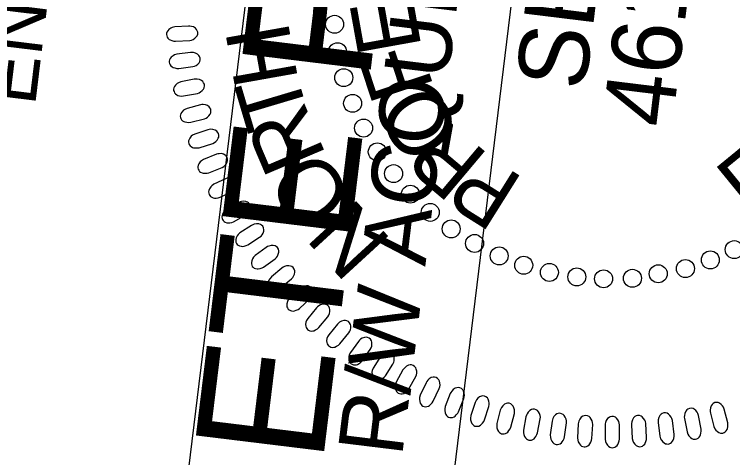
# Model space of a CAD drawing. Extents: x 480344 to 482186, y 488805 to 491553.
# Drawn here: x 480882.7 to 480946.7, y 490486.4 to 490525.8 of the extents above; entities that cross this region are included whole.
import ezdxf

# ---------------------------------------------------------------- set-up
doc = ezdxf.new("R2010")
doc.units = 0
for name, color, linetype in [('Sheet PE Seal Cell', 7, 'Continuous'), ('Sheet Plan CELL', 7, 'Continuous'), ('Sheet Sticker Incomplete CELL', 7, 'Continuous')]:
    doc.layers.add(name, color=color, linetype=linetype)

msp = doc.modelspace()

# ---------------------------------------------------------------- linework, layer by layer
at = {"layer": 'Sheet PE Seal Cell'}
for points in [[(480898.231, 490524.802), (480897.008, 490524.72), (480896.791, 490524.668), (480896.655, 490524.607), (480896.494, 490524.483), (480896.391, 490524.38), (480896.318, 490524.262), (480896.286, 490524.155), (480896.273, 490524.042), (480896.3, 490523.931), (480896.339, 490523.814), (480896.405, 490523.714), (480896.512, 490523.615), (480896.595, 490523.561), (480896.749, 490523.504), (480896.932, 490523.457), (480897.093, 490523.445), (480898.347, 490523.521), (480898.515, 490523.555), (480898.651, 490523.608), (480898.804, 490523.709), (480898.936, 490523.83), (480899.009, 490523.932), (480899.058, 490524.093), (480899.068, 490524.243), (480899.018, 490524.39), (480898.962, 490524.491), (480898.854, 490524.611), (480898.677, 490524.719), (480898.493, 490524.774), (480898.362, 490524.795)], [(480898.421, 490522.456), (480897.204, 490522.298), (480896.992, 490522.233), (480896.859, 490522.163), (480896.706, 490522.029), (480896.61, 490521.919), (480896.545, 490521.798), (480896.519, 490521.688), (480896.514, 490521.575), (480896.548, 490521.466), (480896.593, 490521.351), (480896.666, 490521.255), (480896.779, 490521.164), (480896.865, 490521.115), (480897.023, 490521.068), (480897.208, 490521.032), (480897.369, 490521.03), (480898.616, 490521.185), (480898.781, 490521.229), (480898.914, 490521.292), (480899.061, 490521.401), (480899.185, 490521.531), (480899.251, 490521.637), (480899.291, 490521.801), (480899.291, 490521.951), (480899.232, 490522.095), (480899.169, 490522.192), (480899.054, 490522.305), (480898.87, 490522.401), (480898.683, 490522.445), (480898.552, 490522.458)], [(480898.754, 490520.065), (480897.55, 490519.83), (480897.342, 490519.752), (480897.215, 490519.674), (480897.069, 490519.531), (480896.98, 490519.415), (480896.923, 490519.29), (480896.904, 490519.179), (480896.906, 490519.065), (480896.947, 490518.959), (480896.999, 490518.848), (480897.078, 490518.756), (480897.196, 490518.672), (480897.286, 490518.629), (480897.445, 490518.591), (480897.633, 490518.567), (480897.794, 490518.575), (480899.029, 490518.808), (480899.191, 490518.863), (480899.319, 490518.934), (480899.459, 490519.052), (480899.574, 490519.189), (480899.634, 490519.299), (480899.663, 490519.465), (480899.654, 490519.615), (480899.586, 490519.755), (480899.517, 490519.848), (480899.395, 490519.953), (480899.206, 490520.038), (480899.017, 490520.07), (480898.884, 490520.075)], [(480899.297, 490517.781), (480898.11, 490517.471), (480897.907, 490517.38), (480897.785, 490517.294), (480897.65, 490517.143), (480897.568, 490517.021), (480897.519, 490516.893), (480897.507, 490516.781), (480897.517, 490516.668), (480897.564, 490516.564), (480897.623, 490516.456), (480897.707, 490516.37), (480897.83, 490516.293), (480897.922, 490516.256), (480898.084, 490516.228), (480898.273, 490516.216), (480898.433, 490516.234), (480899.651, 490516.545), (480899.809, 490516.609), (480899.933, 490516.688), (480900.065, 490516.815), (480900.171, 490516.958), (480900.224, 490517.072), (480900.243, 490517.24), (480900.224, 490517.389), (480900.147, 490517.524), (480900.073, 490517.612), (480899.944, 490517.71), (480899.75, 490517.784), (480899.559, 490517.803), (480899.426, 490517.799)], [(480899.967, 490515.566), (480898.801, 490515.183), (480898.605, 490515.079), (480898.488, 490514.985), (480898.362, 490514.826), (480898.289, 490514.699), (480898.248, 490514.568), (480898.243, 490514.456), (480898.259, 490514.343), (480898.313, 490514.243), (480898.378, 490514.139), (480898.468, 490514.058), (480898.595, 490513.989), (480898.69, 490513.958), (480898.853, 490513.94), (480899.043, 490513.94), (480899.201, 490513.968), (480900.396, 490514.354), (480900.551, 490514.428), (480900.67, 490514.515), (480900.793, 490514.65), (480900.891, 490514.8), (480900.936, 490514.917), (480900.943, 490515.085), (480900.916, 490515.234), (480900.831, 490515.363), (480900.751, 490515.447), (480900.617, 490515.536), (480900.419, 490515.597), (480900.227, 490515.605), (480900.094, 490515.593)], [(480900.721, 490513.376), (480899.582, 490512.919), (480899.391, 490512.803), (480899.282, 490512.703), (480899.166, 490512.536), (480899.1, 490512.405), (480899.067, 490512.271), (480899.07, 490512.159), (480899.093, 490512.048), (480899.153, 490511.951), (480899.225, 490511.851), (480899.319, 490511.776), (480899.451, 490511.716), (480899.547, 490511.69), (480899.711, 490511.683), (480899.9, 490511.694), (480900.057, 490511.733), (480901.226, 490512.193), (480901.375, 490512.277), (480901.488, 490512.371), (480901.602, 490512.513), (480901.691, 490512.669), (480901.729, 490512.789), (480901.726, 490512.957), (480901.689, 490513.103), (480901.596, 490513.227), (480901.511, 490513.306), (480901.371, 490513.387), (480901.169, 490513.434), (480900.978, 490513.43), (480900.846, 490513.41)], [(480901.61, 490511.235), (480900.502, 490510.708), (480900.319, 490510.58), (480900.216, 490510.473), (480900.11, 490510.299), (480900.053, 490510.164), (480900.029, 490510.029), (480900.038, 490509.917), (480900.069, 490509.807), (480900.134, 490509.714), (480900.213, 490509.619), (480900.312, 490509.55), (480900.447, 490509.499), (480900.544, 490509.479), (480900.709, 490509.482), (480900.896, 490509.506), (480901.05, 490509.553), (480902.189, 490510.086), (480902.332, 490510.179), (480902.439, 490510.28), (480902.544, 490510.429), (480902.622, 490510.59), (480902.653, 490510.712), (480902.639, 490510.88), (480902.593, 490511.023), (480902.493, 490511.141), (480902.403, 490511.215), (480902.259, 490511.287), (480902.054, 490511.322), (480901.862, 490511.305), (480901.733, 490511.277)], [(480902.712, 490509.085), (480901.639, 490508.489), (480901.465, 490508.35), (480901.368, 490508.237), (480901.274, 490508.056), (480901.226, 490507.918), (480901.21, 490507.782), (480901.226, 490507.67), (480901.263, 490507.563), (480901.335, 490507.475), (480901.419, 490507.385), (480901.522, 490507.322), (480901.66, 490507.279), (480901.759, 490507.265), (480901.923, 490507.279), (480902.108, 490507.314), (480902.259, 490507.372), (480903.361, 490507.974), (480903.499, 490508.077), (480903.599, 490508.183), (480903.695, 490508.339), (480903.763, 490508.505), (480903.786, 490508.629), (480903.762, 490508.795), (480903.706, 490508.935), (480903.599, 490509.047), (480903.505, 490509.114), (480903.356, 490509.177), (480903.15, 490509.199), (480902.96, 490509.171), (480902.832, 490509.134)], [(480903.862, 490507.049), (480902.829, 490506.388), (480902.665, 490506.238), (480902.575, 490506.119), (480902.493, 490505.933), (480902.452, 490505.793), (480902.446, 490505.655), (480902.469, 490505.545), (480902.513, 490505.44), (480902.59, 490505.356), (480902.68, 490505.272), (480902.786, 490505.215), (480902.927, 490505.181), (480903.026, 490505.174), (480903.189, 490505.198), (480903.372, 490505.244), (480903.519, 490505.312), (480904.581, 490505.982), (480904.712, 490506.093), (480904.805, 490506.206), (480904.891, 490506.367), (480904.948, 490506.537), (480904.963, 490506.662), (480904.929, 490506.827), (480904.865, 490506.963), (480904.75, 490507.067), (480904.652, 490507.129), (480904.5, 490507.182), (480904.293, 490507.191), (480904.105, 490507.151), (480903.98, 490507.106)], [(480905.173, 490505.088), (480904.184, 490504.364), (480904.028, 490504.204), (480903.946, 490504.079), (480903.876, 490503.888), (480903.845, 490503.746), (480903.847, 490503.608), (480903.877, 490503.5), (480903.927, 490503.397), (480904.009, 490503.319), (480904.104, 490503.24), (480904.214, 490503.191), (480904.357, 490503.165), (480904.456, 490503.164), (480904.617, 490503.198), (480904.797, 490503.256), (480904.938, 490503.332), (480905.957, 490504.069), (480906.081, 490504.187), (480906.166, 490504.305), (480906.242, 490504.472), (480906.289, 490504.646), (480906.296, 490504.771), (480906.251, 490504.933), (480906.179, 490505.065), (480906.058, 490505.162), (480905.956, 490505.217), (480905.801, 490505.261), (480905.594, 490505.258), (480905.409, 490505.205), (480905.287, 490505.153)], [(480906.569, 490503.243), (480905.627, 490502.458), (480905.482, 490502.288), (480905.409, 490502.159), (480905.35, 490501.964), (480905.328, 490501.819), (480905.339, 490501.682), (480905.375, 490501.576), (480905.432, 490501.477), (480905.518, 490501.404), (480905.618, 490501.331), (480905.731, 490501.289), (480905.875, 490501.272), (480905.974, 490501.278), (480906.133, 490501.321), (480906.308, 490501.391), (480906.446, 490501.475), (480907.416, 490502.275), (480907.531, 490502.4), (480907.61, 490502.524), (480907.675, 490502.696), (480907.71, 490502.871), (480907.71, 490502.997), (480907.655, 490503.156), (480907.574, 490503.283), (480907.448, 490503.372), (480907.343, 490503.421), (480907.185, 490503.455), (480906.978, 490503.438), (480906.797, 490503.375), (480906.679, 490503.315)], [(480908.147, 490501.425), (480907.256, 490500.582), (480907.123, 490500.404), (480907.057, 490500.27), (480907.011, 490500.072), (480906.998, 490499.926), (480907.017, 490499.79), (480907.06, 490499.687), (480907.123, 490499.591), (480907.214, 490499.523), (480907.319, 490499.458), (480907.433, 490499.422), (480907.578, 490499.415), (480907.677, 490499.426), (480907.832, 490499.48), (480908.004, 490499.56), (480908.135, 490499.653), (480909.053, 490500.512), (480909.161, 490500.645), (480909.231, 490500.773), (480909.285, 490500.948), (480909.309, 490501.125), (480909.3, 490501.251), (480909.236, 490501.406), (480909.148, 490501.528), (480909.016, 490501.609), (480908.908, 490501.651), (480908.748, 490501.675), (480908.543, 490501.645), (480908.366, 490501.571), (480908.252, 490501.503)], [(480909.652, 490499.705), (480908.866, 490498.764), (480908.755, 490498.571), (480908.705, 490498.43), (480908.683, 490498.228), (480908.687, 490498.082), (480908.722, 490497.949), (480908.777, 490497.852), (480908.85, 490497.764), (480908.949, 490497.707), (480909.06, 490497.654), (480909.179, 490497.632), (480909.323, 490497.642), (480909.42, 490497.665), (480909.567, 490497.737), (480909.729, 490497.837), (480909.848, 490497.945), (480910.659, 490498.905), (480910.75, 490499.049), (480910.805, 490499.185), (480910.838, 490499.366), (480910.842, 490499.544), (480910.817, 490499.668), (480910.736, 490499.814), (480910.634, 490499.925), (480910.493, 490499.991), (480910.381, 490500.019), (480910.22, 490500.024), (480910.02, 490499.971), (480909.853, 490499.876), (480909.747, 490499.795)], [(480911.513, 490498.255), (480910.735, 490497.307), (480910.624, 490497.114), (480910.576, 490496.973), (480910.554, 490496.77), (480910.56, 490496.623), (480910.596, 490496.491), (480910.652, 490496.394), (480910.726, 490496.307), (480910.826, 490496.251), (480910.937, 490496.199), (480911.056, 490496.178), (480911.2, 490496.189), (480911.297, 490496.212), (480911.444, 490496.286), (480911.604, 490496.386), (480911.722, 490496.496), (480912.525, 490497.462), (480912.616, 490497.608), (480912.67, 490497.744), (480912.701, 490497.924), (480912.703, 490498.103), (480912.679, 490498.226), (480912.595, 490498.372), (480912.492, 490498.482), (480912.352, 490498.546), (480912.239, 490498.574), (480912.077, 490498.578), (480911.878, 490498.523), (480911.712, 490498.427), (480911.606, 490498.346)], [(480913.389, 490496.712), (480912.671, 490495.717), (480912.574, 490495.518), (480912.534, 490495.373), (480912.526, 490495.17), (480912.541, 490495.024), (480912.585, 490494.894), (480912.647, 490494.801), (480912.726, 490494.719), (480912.829, 490494.67), (480912.943, 490494.624), (480913.063, 490494.611), (480913.206, 490494.631), (480913.301, 490494.661), (480913.443, 490494.743), (480913.597, 490494.853), (480913.709, 490494.97), (480914.449, 490495.985), (480914.53, 490496.135), (480914.575, 490496.275), (480914.596, 490496.457), (480914.587, 490496.636), (480914.554, 490496.757), (480914.462, 490496.898), (480914.352, 490497.001), (480914.208, 490497.056), (480914.094, 490497.077), (480913.932, 490497.071), (480913.736, 490497.003), (480913.577, 490496.897), (480913.477, 490496.809)], [(480915.363, 490495.354), (480914.709, 490494.316), (480914.624, 490494.111), (480914.593, 490493.964), (480914.598, 490493.761), (480914.622, 490493.616), (480914.675, 490493.489), (480914.742, 490493.4), (480914.826, 490493.323), (480914.932, 490493.28), (480915.049, 490493.242), (480915.169, 490493.237), (480915.311, 490493.266), (480915.404, 490493.301), (480915.541, 490493.392), (480915.687, 490493.512), (480915.791, 490493.635), (480916.467, 490494.695), (480916.538, 490494.85), (480916.574, 490494.992), (480916.583, 490495.175), (480916.562, 490495.353), (480916.523, 490495.472), (480916.422, 490495.607), (480916.306, 490495.703), (480916.158, 490495.749), (480916.043, 490495.762), (480915.883, 490495.746), (480915.691, 490495.666), (480915.539, 490495.55), (480915.444, 490495.456)], [(480917.352, 490494.165), (480916.765, 490493.088), (480916.693, 490492.877), (480916.672, 490492.73), (480916.689, 490492.527), (480916.722, 490492.384), (480916.783, 490492.261), (480916.856, 490492.176), (480916.945, 490492.104), (480917.052, 490492.069), (480917.172, 490492.038), (480917.292, 490492.039), (480917.431, 490492.077), (480917.523, 490492.119), (480917.653, 490492.218), (480917.791, 490492.347), (480917.887, 490492.476), (480918.495, 490493.576), (480918.556, 490493.736), (480918.584, 490493.88), (480918.582, 490494.063), (480918.55, 490494.239), (480918.503, 490494.356), (480918.394, 490494.484), (480918.272, 490494.572), (480918.122, 490494.609), (480918.005, 490494.615), (480917.846, 490494.589), (480917.661, 490494.497), (480917.515, 490494.371), (480917.427, 490494.271)], [(480919.419, 490493.03), (480918.901, 490491.918), (480918.842, 490491.704), (480918.83, 490491.555), (480918.86, 490491.354), (480918.902, 490491.213), (480918.97, 490491.094), (480919.048, 490491.014), (480919.141, 490490.948), (480919.251, 490490.919), (480919.372, 490490.895), (480919.492, 490490.905), (480919.629, 490490.951), (480919.717, 490490.999), (480919.842, 490491.106), (480919.971, 490491.243), (480920.059, 490491.378), (480920.597, 490492.514), (480920.648, 490492.678), (480920.666, 490492.823), (480920.652, 490493.006), (480920.609, 490493.179), (480920.556, 490493.293), (480920.439, 490493.414), (480920.311, 490493.495), (480920.159, 490493.521), (480920.043, 490493.52), (480919.886, 490493.484), (480919.706, 490493.381), (480919.569, 490493.246), (480919.487, 490493.141)], [(480921.572, 490492.058), (480921.125, 490490.915), (480921.08, 490490.698), (480921.077, 490490.548), (480921.12, 490490.349), (480921.171, 490490.212), (480921.246, 490490.096), (480921.329, 490490.021), (480921.426, 490489.962), (480921.537, 490489.939), (480921.66, 490489.924), (480921.78, 490489.941), (480921.913, 490489.996), (480921.998, 490490.048), (480922.115, 490490.164), (480922.236, 490490.309), (480922.315, 490490.449), (480922.781, 490491.617), (480922.821, 490491.783), (480922.83, 490491.929), (480922.805, 490492.11), (480922.752, 490492.281), (480922.69, 490492.391), (480922.566, 490492.504), (480922.434, 490492.577), (480922.28, 490492.594), (480922.164, 490492.586), (480922.01, 490492.539), (480921.837, 490492.425), (480921.708, 490492.283), (480921.634, 490492.172)], [(480923.789, 490491.272), (480923.415, 490490.104), (480923.383, 490489.884), (480923.389, 490489.734), (480923.445, 490489.538), (480923.504, 490489.404), (480923.587, 490489.294), (480923.674, 490489.225), (480923.774, 490489.171), (480923.887, 490489.156), (480924.01, 490489.148), (480924.128, 490489.173), (480924.258, 490489.236), (480924.34, 490489.294), (480924.45, 490489.415), (480924.562, 490489.568), (480924.631, 490489.713), (480925.023, 490490.908), (480925.053, 490491.076), (480925.052, 490491.223), (480925.016, 490491.402), (480924.952, 490491.569), (480924.884, 490491.675), (480924.753, 490491.78), (480924.616, 490491.845), (480924.461, 490491.852), (480924.347, 490491.836), (480924.195, 490491.78), (480924.029, 490491.656), (480923.91, 490491.505), (480923.842, 490491.39)], [(480926.035, 490490.574), (480925.735, 490489.385), (480925.717, 490489.163), (480925.733, 490489.014), (480925.801, 490488.823), (480925.868, 490488.692), (480925.957, 490488.588), (480926.049, 490488.523), (480926.153, 490488.476), (480926.266, 490488.469), (480926.39, 490488.468), (480926.506, 490488.5), (480926.632, 490488.572), (480926.709, 490488.635), (480926.811, 490488.763), (480926.913, 490488.922), (480926.974, 490489.072), (480927.289, 490490.288), (480927.309, 490490.458), (480927.299, 490490.604), (480927.252, 490490.78), (480927.177, 490490.944), (480927.102, 490491.045), (480926.965, 490491.141), (480926.824, 490491.198), (480926.67, 490491.195), (480926.556, 490491.172), (480926.409, 490491.107), (480926.251, 490490.972), (480926.142, 490490.814), (480926.082, 490490.696)], [(480942.452, 490489.846), (480942.687, 490488.642), (480942.765, 490488.433), (480942.842, 490488.306), (480942.986, 490488.161), (480943.102, 490488.072), (480943.227, 490488.015), (480943.337, 490487.996), (480943.451, 490487.998), (480943.557, 490488.039), (480943.669, 490488.091), (480943.76, 490488.17), (480943.844, 490488.288), (480943.888, 490488.377), (480943.925, 490488.537), (480943.949, 490488.725), (480943.941, 490488.886), (480943.708, 490490.121), (480943.654, 490490.283), (480943.583, 490490.411), (480943.465, 490490.55), (480943.328, 490490.666), (480943.217, 490490.726), (480943.052, 490490.755), (480942.901, 490490.746), (480942.762, 490490.678), (480942.669, 490490.609), (480942.563, 490490.487), (480942.478, 490490.298), (480942.446, 490490.109), (480942.442, 490489.976)], [(480944.765, 490490.328), (480945.074, 490489.141), (480945.166, 490488.937), (480945.251, 490488.815), (480945.403, 490488.68), (480945.525, 490488.598), (480945.654, 490488.549), (480945.764, 490488.537), (480945.878, 490488.546), (480945.981, 490488.593), (480946.09, 490488.653), (480946.176, 490488.736), (480946.252, 490488.86), (480946.29, 490488.952), (480946.317, 490489.114), (480946.329, 490489.303), (480946.311, 490489.463), (480946.001, 490490.681), (480945.937, 490490.839), (480945.858, 490490.963), (480945.731, 490491.094), (480945.587, 490491.201), (480945.473, 490491.254), (480945.306, 490491.273), (480945.156, 490491.254), (480945.022, 490491.178), (480944.933, 490491.103), (480944.835, 490490.975), (480944.763, 490490.78), (480944.742, 490490.589), (480944.747, 490490.456)], [(480928.327, 490490.006), (480928.102, 490488.8), (480928.098, 490488.577), (480928.124, 490488.43), (480928.203, 490488.243), (480928.278, 490488.117), (480928.374, 490488.018), (480928.47, 490487.96), (480928.576, 490487.919), (480928.69, 490487.919), (480928.814, 490487.926), (480928.927, 490487.965), (480929.048, 490488.044), (480929.122, 490488.112), (480929.215, 490488.246), (480929.307, 490488.412), (480929.358, 490488.565), (480929.597, 490489.799), (480929.606, 490489.969), (480929.587, 490490.115), (480929.528, 490490.288), (480929.444, 490490.446), (480929.363, 490490.542), (480929.219, 490490.63), (480929.076, 490490.677), (480928.922, 490490.665), (480928.81, 490490.635), (480928.666, 490490.561), (480928.518, 490490.416), (480928.418, 490490.252), (480928.366, 490490.13)], [(480930.645, 490489.591), (480930.496, 490488.374), (480930.507, 490488.152), (480930.541, 490488.006), (480930.632, 490487.825), (480930.715, 490487.703), (480930.817, 490487.611), (480930.916, 490487.559), (480931.025, 490487.525), (480931.138, 490487.532), (480931.261, 490487.547), (480931.372, 490487.593), (480931.488, 490487.68), (480931.557, 490487.751), (480931.642, 490487.892), (480931.723, 490488.063), (480931.765, 490488.218), (480931.925, 490489.465), (480931.923, 490489.635), (480931.895, 490489.78), (480931.826, 490489.949), (480931.732, 490490.101), (480931.645, 490490.192), (480931.496, 490490.271), (480931.35, 490490.309), (480931.197, 490490.287), (480931.087, 490490.25), (480930.949, 490490.167), (480930.809, 490490.013), (480930.721, 490489.843), (480930.675, 490489.718)], [(480932.992, 490489.358), (480932.919, 490488.133), (480932.944, 490487.912), (480932.987, 490487.769), (480933.089, 490487.593), (480933.18, 490487.477), (480933.287, 490487.391), (480933.389, 490487.346), (480933.5, 490487.319), (480933.613, 490487.333), (480933.735, 490487.356), (480933.842, 490487.409), (480933.953, 490487.503), (480934.017, 490487.579), (480934.093, 490487.724), (480934.163, 490487.9), (480934.195, 490488.057), (480934.277, 490489.311), (480934.264, 490489.482), (480934.227, 490489.624), (480934.147, 490489.789), (480934.044, 490489.934), (480933.952, 490490.02), (480933.799, 490490.089), (480933.65, 490490.118), (480933.499, 490490.087), (480933.391, 490490.043), (480933.259, 490489.951), (480933.129, 490489.789), (480933.051, 490489.613), (480933.014, 490489.486)], [(480937.724, 490489.281), (480937.806, 490488.057), (480937.857, 490487.841), (480937.918, 490487.705), (480938.042, 490487.543), (480938.146, 490487.44), (480938.263, 490487.368), (480938.37, 490487.335), (480938.484, 490487.323), (480938.594, 490487.35), (480938.711, 490487.388), (480938.812, 490487.454), (480938.91, 490487.561), (480938.964, 490487.645), (480939.021, 490487.799), (480939.069, 490487.982), (480939.081, 490488.142), (480939.005, 490489.397), (480938.971, 490489.564), (480938.917, 490489.701), (480938.817, 490489.853), (480938.695, 490489.986), (480938.593, 490490.059), (480938.433, 490490.108), (480938.282, 490490.118), (480938.136, 490490.068), (480938.034, 490490.012), (480937.914, 490489.904), (480937.807, 490489.727), (480937.751, 490489.542), (480937.73, 490489.412)], [(480940.106, 490489.474), (480940.264, 490488.257), (480940.33, 490488.045), (480940.399, 490487.912), (480940.532, 490487.759), (480940.643, 490487.662), (480940.765, 490487.598), (480940.873, 490487.572), (480940.987, 490487.567), (480941.095, 490487.601), (480941.21, 490487.646), (480941.306, 490487.719), (480941.397, 490487.832), (480941.447, 490487.918), (480941.494, 490488.075), (480941.53, 490488.261), (480941.532, 490488.422), (480941.377, 490489.669), (480941.333, 490489.835), (480941.27, 490489.967), (480941.16, 490490.113), (480941.032, 490490.238), (480940.925, 490490.304), (480940.761, 490490.343), (480940.61, 490490.344), (480940.468, 490490.285), (480940.37, 490490.222), (480940.256, 490490.107), (480940.161, 490489.923), (480940.116, 490489.736), (480940.104, 490489.604)], [(480935.375, 490489.232), (480935.379, 490488.006), (480935.418, 490487.787), (480935.47, 490487.647), (480935.583, 490487.478), (480935.681, 490487.368), (480935.794, 490487.289), (480935.898, 490487.25), (480936.011, 490487.23), (480936.122, 490487.251), (480936.242, 490487.281), (480936.347, 490487.341), (480936.451, 490487.442), (480936.511, 490487.522), (480936.577, 490487.671), (480936.636, 490487.851), (480936.658, 490488.01), (480936.661, 490489.267), (480936.638, 490489.436), (480936.592, 490489.576), (480936.502, 490489.735), (480936.39, 490489.874), (480936.292, 490489.954), (480936.135, 490490.013), (480935.985, 490490.032), (480935.836, 490489.992), (480935.731, 490489.942), (480935.604, 490489.842), (480935.486, 490489.672), (480935.419, 490489.492), (480935.39, 490489.362)]]:
    msp.add_lwpolyline(points, close=True, dxfattribs=at)
for centre in [(480911.26, 490524.958), (480911.523, 490522.519), (480912.083, 490520.204), (480912.872, 490517.917), (480913.846, 490515.712), (480915.072, 490513.596), (480916.52, 490511.654), (480918.022, 490509.826), (480919.79, 490508.205), (480921.656, 490506.733), (480923.745, 490505.435), (480946.892, 490504.885), (480925.937, 490504.324), (480928.123, 490503.495), (480944.761, 490503.968), (480930.412, 490502.853), (480940.115, 490502.732), (480942.54, 490503.197), (480932.857, 490502.457), (480935.244, 490502.285), (480937.818, 490502.331)]:
    msp.add_circle(centre, 0.801, dxfattribs=at)
at = {"layer": 'Sheet Sticker Incomplete CELL'}
msp.add_lwpolyline([(480912.202, 490405.709), (480888.876, 490408.558), (480906.698, 490554.474), (480930.024, 490551.625)], close=True, dxfattribs=at)

# ---------------------------------------------------------------- texts
at = {"layer": 'Sheet PE Seal Cell'}
for s, height, rotation, p in [('SEAL', 6.2363, 83.01787, (480933.596, 490518.955)), ('46155', 6.2363, 83.01787, (480941.331, 490515.645)), ('E', 5.669, 100.20514, (480919.029, 490522.867)), ('H', 5.669, 100.09226, (480908.029, 490519.983)), ('F', 5.669, 108.14494, (480920.145, 490519.315)), ('T', 5.669, 106.58162, (480909.043, 490516.656)), ('O', 5.669, 124.02453, (480922.812, 490515.265)), ('R', 5.669, 113.07097, (480910.557, 490513.227)), ('R', 5.669, 139.90413, (480925.132, 490513.255)), ('E', 5.669, 39.3021, (480948.451, 490507.469)), ('O', 5.669, 126.04969, (480913.142, 490509.41)), ('P', 5.669, 147.84392, (480928.264, 490511.173)), ('N', 5.669, 132.53904, (480916.463, 490505.632))]:
    msp.add_text(s, height=height, rotation=rotation, dxfattribs=at).set_placement(p)
at = {"layer": 'Sheet Plan CELL'}
msp.add_text('ENGINEER', height=5.0001, rotation=83.03652, dxfattribs=at).set_placement((480884.553, 490517.612))
at = {"layer": 'Sheet Sticker Incomplete CELL'}
for s, height, p in [('INCOMPLETE PLANS', 11.52, (480901.674, 490416.012)), ('DO NOT USE FOR R/W ACQUISITION', 5.76, (480908.967, 490418.395))]:
    msp.add_text(s, height=height, rotation=83.03651, dxfattribs=at).set_placement(p)

doc.saveas('drawing.dxf')
